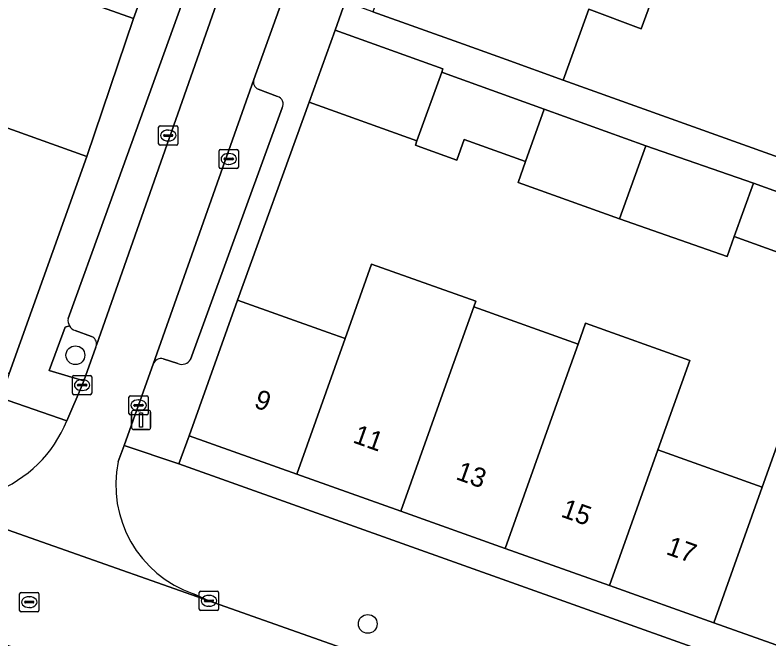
# Model space of a CAD drawing. Extents: x 159817 to 160765, y 380688 to 381638.
# Drawn here: x 160125.52 to 160164.67, y 381145.69 to 381178.1 of the extents above; entities that cross this region are included whole.
import ezdxf

# ---------------------------------------------------------------- set-up
doc = ezdxf.new("R2010")
doc.units = 0
for name, color, linetype in [('IMGEO_Boom', 7, 'Continuous'), ('IMGEO_Erf', 7, 'Continuous'), ('IMGEO_Groenvoorziening', 7, 'Continuous'), ('IMGEO_Kolk', 7, 'Continuous'), ('IMGEO_Lichtmast', 7, 'Continuous'), ('IMGEO_Muur', 7, 'Continuous'), ('IMGEO_Pand', 7, 'Continuous'), ('IMGEO_Pand_nummerreeks', 7, 'Continuous'), ('IMGEO_Parkeervlak_open', 7, 'Continuous'), ('IMGEO_Rijbaan_lokaal_open', 7, 'Continuous'), ('IMGEO_Rioolput', 7, 'Continuous'), ('IMGEO_Voetpad_open', 7, 'Continuous')]:
    doc.layers.add(name, color=color, linetype=linetype)

msp = doc.modelspace()

# ---------------------------------------------------------------- linework, layer by layer
at = {"layer": 'IMGEO_Boom'}
for centre in [(160128.655, 381160.427), (160143.838, 381146.472)]:
    msp.add_circle(centre, 0.489, dxfattribs=at)
at = {"layer": 'IMGEO_Erf'}
for points in [[(160166.279, 381209.298), (160163.437, 381210.329), (160161.369, 381204.579), (160164.234, 381203.614), (160162.154, 381197.83), (160163.066, 381197.502), (160161.69, 381193.674), (160164.512, 381192.675), (160163.836, 381190.794), (160160.049, 381192.134), (160157.986, 381186.396), (160159.888, 381185.712), (160158.664, 381182.309), (160161.844, 381181.165), (160160.986, 381178.778), (160158.826, 381179.555), (160158.045, 381177.383), (160155.316, 381178.399), (160153.991, 381174.716), (160170.088, 381168.945)], [(160123.783, 381172.701), (160129.244, 381170.748), (160131.673, 381177.921), (160128.045, 381179.223), (160126.309, 381179.846), (160127.288, 381182.577), (160125.277, 381183.178)], [(160166.219, 381165.378), (160162.869, 381166.591), (160162.497, 381165.563), (160156.911, 381167.504), (160151.65, 381169.403), (160152.036, 381170.487), (160148.85, 381171.637), (160148.464, 381170.553), (160146.587, 381171.231), (160146.312, 381171.33), (160146.394, 381171.558), (160140.795, 381173.569), (160137.079, 381163.29), (160141.789, 381161.611), (160142.658, 381161.3), (160144.034, 381165.16), (160149.449, 381163.23), (160149.345, 381162.937), (160154.762, 381161.006), (160155.149, 381162.091), (160160.566, 381160.16), (160158.907, 381155.508), (160164.323, 381153.577), (160166.602, 381159.968)]]:
    msp.add_lwpolyline(points, dxfattribs=at)
msp.add_lwpolyline([(160156.395, 381148.463), (160150.978, 381150.394), (160145.562, 381152.324), (160140.147, 381154.254), (160134.567, 381156.243), (160134.027, 381154.785), (160177.694, 381139.196), (160178.225, 381140.682), (160172.644, 381142.671), (160167.227, 381144.602), (160161.811, 381146.532)], close=True, dxfattribs=at)
at = {"layer": 'IMGEO_Groenvoorziening'}
for points in [[(160128.349, 381161.952), (160128.116, 381161.877), (160127.292, 381159.634), (160129.085, 381159.092), (160129.721, 381160.851)], [(160129.491, 381161.399), (160128.646, 381161.704)]]:
    msp.add_lwpolyline(points, dxfattribs=at)
for centre, radius, start, end in [((160128.851, 381162.251), 0.584, 210.7946, 249.4805), ((160129.342, 381161.014), 0.413, 350.1632, 68.7554), ((160129.293, 381161.026), 0.463, 337.8043, 349.8172)]:
    msp.add_arc(centre, radius, start, end, dxfattribs=at)
at = {"layer": 'IMGEO_Kolk'}
for p, q in [((160132.977, 381171.413), (160132.977, 381172.265)), ((160133.052, 381172.339), (160133.904, 381172.339)), ((160133.978, 381172.265), (160133.978, 381171.413)), ((160133.279, 381171.882), (160133.677, 381171.882)), ((160133.465, 381172.119), (160133.49, 381172.119)), ((160133.236, 381171.833), (160133.236, 381171.845)), ((160133.674, 381171.796), (160133.276, 381171.796)), ((160133.488, 381171.559), (160133.463, 381171.559)), ((160133.72, 381171.845), (160133.72, 381171.833)), ((160133.904, 381171.339), (160133.052, 381171.339)), ((160136.191, 381171.121), (160137.043, 381171.121)), ((160136.116, 381170.195), (160136.116, 381171.047)), ((160136.604, 381170.901), (160136.629, 381170.901)), ((160137.117, 381171.047), (160137.117, 381170.195)), ((160136.375, 381170.615), (160136.375, 381170.627)), ((160136.813, 381170.578), (160136.415, 381170.578)), ((160136.418, 381170.664), (160136.816, 381170.664)), ((160136.627, 381170.341), (160136.602, 381170.341)), ((160136.859, 381170.627), (160136.859, 381170.615)), ((160137.043, 381170.121), (160136.191, 381170.121)), ((160128.577, 381159.376), (160129.429, 381159.376)), ((160128.502, 381158.45), (160128.502, 381159.302)), ((160128.99, 381159.156), (160129.015, 381159.156)), ((160129.503, 381159.302), (160129.503, 381158.45)), ((160128.761, 381158.87), (160128.761, 381158.882)), ((160129.199, 381158.833), (160128.801, 381158.833)), ((160128.804, 381158.919), (160129.202, 381158.919)), ((160129.013, 381158.596), (160128.988, 381158.596)), ((160129.245, 381158.882), (160129.245, 381158.87)), ((160129.429, 381158.376), (160128.577, 381158.376)), ((160131.437, 381157.399), (160131.437, 381158.251)), ((160131.512, 381158.325), (160132.364, 381158.325)), ((160132.438, 381158.251), (160132.438, 381157.399)), ((160131.696, 381157.819), (160131.696, 381157.831)), ((160132.134, 381157.782), (160131.736, 381157.782)), ((160131.739, 381157.868), (160132.137, 381157.868)), ((160131.925, 381158.105), (160131.95, 381158.105)), ((160132.18, 381157.831), (160132.18, 381157.819)), ((160131.948, 381157.545), (160131.923, 381157.545)), ((160132.364, 381157.325), (160131.512, 381157.325)), ((160135.089, 381147.243), (160135.089, 381148.095)), ((160135.164, 381148.169), (160136.016, 381148.169)), ((160136.09, 381148.095), (160136.09, 381147.243)), ((160135.348, 381147.663), (160135.348, 381147.675)), ((160135.786, 381147.626), (160135.388, 381147.626)), ((160135.391, 381147.712), (160135.789, 381147.712)), ((160135.577, 381147.949), (160135.602, 381147.949)), ((160135.832, 381147.675), (160135.832, 381147.663)), ((160135.6, 381147.389), (160135.575, 381147.389)), ((160136.016, 381147.169), (160135.164, 381147.169))]:
    msp.add_line(p, q, dxfattribs=at)
for points in [[(160132.977, 381171.413), (160132.977, 381172.265)], [(160133.052, 381172.339), (160133.904, 381172.339)], [(160133.978, 381172.265), (160133.978, 381171.413)], [(160133.904, 381171.339), (160133.052, 381171.339)], [(160136.191, 381171.121), (160137.043, 381171.121)], [(160136.116, 381170.195), (160136.116, 381171.047)], [(160137.117, 381171.047), (160137.117, 381170.195)], [(160137.043, 381170.121), (160136.191, 381170.121)], [(160128.577, 381159.376), (160129.429, 381159.376)], [(160128.502, 381158.45), (160128.502, 381159.302)], [(160129.503, 381159.302), (160129.503, 381158.45)], [(160129.429, 381158.376), (160128.577, 381158.376)], [(160131.437, 381157.399), (160131.437, 381158.251)], [(160131.512, 381158.325), (160132.364, 381158.325)], [(160132.438, 381158.251), (160132.438, 381157.399)], [(160132.364, 381157.325), (160131.512, 381157.325)], [(160135.089, 381147.243), (160135.089, 381148.095)], [(160135.164, 381148.169), (160136.016, 381148.169)], [(160136.09, 381148.095), (160136.09, 381147.243)], [(160136.016, 381147.169), (160135.164, 381147.169)]]:
    msp.add_lwpolyline(points, dxfattribs=at)
for centre, radius, start, end in [((160133.054, 381172.263), 0.0765, 91.552, 178.448), ((160133.054, 381172.263), 0.0765, 91.552, 178.448), ((160133.902, 381172.263), 0.0765, 1.552, 88.448), ((160133.902, 381172.263), 0.0765, 1.552, 88.448), ((160133.276, 381171.842), 0.0403, 85.8775, 175.7526), ((160133.681, 381171.844), 0.0386, 1.7309, 96.639), ((160133.273, 381171.832), 0.0366, 178.938, 274.7102), ((160133.677, 381171.839), 0.043, 264.8664, 352.4533), ((160133.054, 381171.415), 0.0765, 181.552, 268.448), ((160133.054, 381171.415), 0.0765, 181.552, 268.448), ((160133.902, 381171.415), 0.0765, 271.552, 358.448), ((160133.902, 381171.415), 0.0765, 271.552, 358.448), ((160136.193, 381171.045), 0.0765, 91.552, 178.448), ((160136.193, 381171.045), 0.0765, 91.552, 178.448), ((160137.041, 381171.045), 0.0765, 1.552, 88.448), ((160137.041, 381171.045), 0.0765, 1.552, 88.448), ((160136.415, 381170.624), 0.0403, 85.8775, 175.7526), ((160136.412, 381170.614), 0.0366, 178.938, 274.7102), ((160136.816, 381170.621), 0.043, 264.8664, 352.4533), ((160136.82, 381170.626), 0.0386, 1.7309, 96.639), ((160136.193, 381170.197), 0.0765, 181.552, 268.448), ((160136.193, 381170.197), 0.0765, 181.552, 268.448), ((160137.041, 381170.197), 0.0765, 271.552, 358.448), ((160137.041, 381170.197), 0.0765, 271.552, 358.448), ((160128.579, 381159.3), 0.0765, 91.552, 178.448), ((160128.579, 381159.3), 0.0765, 91.552, 178.448), ((160129.427, 381159.3), 0.0765, 1.552, 88.448), ((160129.427, 381159.3), 0.0765, 1.552, 88.448), ((160128.801, 381158.879), 0.0403, 85.8775, 175.7526), ((160128.798, 381158.869), 0.0366, 178.938, 274.7102), ((160129.202, 381158.876), 0.043, 264.8664, 352.4533), ((160129.206, 381158.881), 0.0386, 1.7309, 96.639), ((160128.579, 381158.452), 0.0765, 181.552, 268.448), ((160128.579, 381158.452), 0.0765, 181.552, 268.448), ((160129.427, 381158.452), 0.0765, 271.552, 358.448), ((160129.427, 381158.452), 0.0765, 271.552, 358.448), ((160131.514, 381158.249), 0.0765, 91.552, 178.448), ((160131.514, 381158.249), 0.0765, 91.552, 178.448), ((160132.362, 381158.249), 0.0765, 1.552, 88.448), ((160132.362, 381158.249), 0.0765, 1.552, 88.448), ((160131.736, 381157.828), 0.0403, 85.8775, 175.7526), ((160131.733, 381157.818), 0.0366, 178.938, 274.7102), ((160132.137, 381157.825), 0.043, 264.8664, 352.4533), ((160132.141, 381157.83), 0.0386, 1.7309, 96.639), ((160131.514, 381157.401), 0.0765, 181.552, 268.448), ((160131.514, 381157.401), 0.0765, 181.552, 268.448), ((160132.362, 381157.401), 0.0765, 271.552, 358.448), ((160132.362, 381157.401), 0.0765, 271.552, 358.448), ((160135.166, 381148.093), 0.0765, 91.552, 178.448), ((160135.166, 381148.093), 0.0765, 91.552, 178.448), ((160136.014, 381148.093), 0.0765, 1.552, 88.448), ((160136.014, 381148.093), 0.0765, 1.552, 88.448), ((160135.388, 381147.672), 0.0403, 85.8775, 175.7526), ((160135.385, 381147.662), 0.0366, 178.938, 274.7102), ((160135.789, 381147.669), 0.043, 264.8664, 352.4533), ((160135.793, 381147.674), 0.0386, 1.7309, 96.639), ((160135.166, 381147.245), 0.0765, 181.552, 268.448), ((160135.166, 381147.245), 0.0765, 181.552, 268.448), ((160136.014, 381147.245), 0.0765, 271.552, 358.448), ((160136.014, 381147.245), 0.0765, 271.552, 358.448)]:
    msp.add_arc(centre, radius, start, end, dxfattribs=at)
for centre, major_axis, ratio, start_param, end_param in [((160133.464, 381171.839), (-0.387, 0.002), 0.722429, 4.712389, 7.853982), ((160133.489, 381171.839), (-0.39, 0.002), 0.717154, 1.570796, 4.712389), ((160136.603, 381170.621), (-0.387, 0.002), 0.722429, 4.712389, 7.853982), ((160136.628, 381170.621), (-0.39, 0.002), 0.717154, 1.570796, 4.712389), ((160128.989, 381158.876), (-0.387, 0.002), 0.722429, 4.712389, 7.853982), ((160129.014, 381158.876), (-0.39, 0.002), 0.717154, 1.570796, 4.712389), ((160131.924, 381157.825), (-0.387, 0.002), 0.722429, 4.712389, 7.853982), ((160131.949, 381157.825), (-0.39, 0.002), 0.717154, 1.570796, 4.712389), ((160135.576, 381147.669), (-0.387, 0.002), 0.722429, 4.712389, 7.853982), ((160135.601, 381147.669), (-0.39, 0.002), 0.717154, 1.570796, 4.712389)]:
    msp.add_ellipse(centre, major_axis=major_axis, ratio=ratio, start_param=start_param, end_param=end_param, dxfattribs=at)
at = {"layer": 'IMGEO_Lichtmast'}
for p, q in [((160131.569, 381156.667), (160131.569, 381157.467)), ((160131.569, 381157.467), (160131.569, 381156.667)), ((160131.669, 381157.567), (160132.459, 381157.567)), ((160132.459, 381157.567), (160131.669, 381157.567)), ((160132.559, 381157.467), (160132.559, 381156.667)), ((160132.559, 381156.667), (160132.559, 381157.467)), ((160132.459, 381156.567), (160131.669, 381156.567)), ((160131.669, 381156.567), (160132.459, 381156.567))]:
    msp.add_line(p, q, dxfattribs=at)
msp.add_lwpolyline([(160131.989, 381157.442), (160132.139, 381157.442), (160132.139, 381156.692), (160131.989, 381156.692), (160131.989, 381157.442)], dxfattribs=at)
for centre, start, end in [((160131.669, 381157.467), 90, 180), ((160131.669, 381157.467), 90, 180), ((160132.459, 381157.467), 0, 90), ((160132.459, 381157.467), 360, 90), ((160131.669, 381156.667), 180, 270), ((160131.669, 381156.667), 180, 270), ((160132.459, 381156.667), 270, 0), ((160132.459, 381156.667), 270, 0)]:
    msp.add_arc(centre, 0.1, start, end, dxfattribs=at)
at = {"layer": 'IMGEO_Muur'}
for points in [[(160129.244, 381170.748), (160131.673, 381177.921)], [(160137.079, 381163.29), (160140.795, 381173.569)]]:
    msp.add_lwpolyline(points, dxfattribs=at)
at = {"layer": 'IMGEO_Pand'}
for points in [[(160146.222, 381184.159), (160144.105, 381178.27), (160148.811, 381176.578), (160151.017, 381175.785), (160153.991, 381174.716), (160155.316, 381178.399), (160158.045, 381177.383), (160158.826, 381179.555)], [(160132.686, 381180.746), (160129.058, 381182.048), (160127.561, 381182.585), (160127.322, 381182.671), (160127.288, 381182.577), (160126.309, 381179.846), (160128.045, 381179.223), (160131.673, 381177.921)], [(160147.679, 381175.133), (160147.74, 381175.302), (160142.141, 381177.315), (160140.795, 381173.569), (160146.394, 381171.558)], [(160153.007, 381173.21), (160147.959, 381175.032), (160147.679, 381175.133), (160146.394, 381171.558), (160146.312, 381171.33), (160146.587, 381171.231), (160148.464, 381170.553), (160148.85, 381171.637), (160152.036, 381170.487)], [(160158.283, 381171.305), (160153.007, 381173.21), (160152.036, 381170.487), (160151.65, 381169.403), (160156.911, 381167.504)], [(160123.301, 381171.353), (160119.752, 381161.429), (160125.213, 381159.476), (160129.244, 381170.748), (160123.783, 381172.701)], [(160163.873, 381169.362), (160158.283, 381171.305), (160156.911, 381167.504), (160162.497, 381165.563), (160162.869, 381166.591)], [(160167.223, 381168.149), (160163.873, 381169.362), (160162.869, 381166.591), (160166.219, 381165.378)], [(160148.073, 381159.37), (160149.345, 381162.937), (160149.449, 381163.23), (160144.034, 381165.16), (160142.658, 381161.3), (160140.147, 381154.254), (160145.562, 381152.324)], [(160140.147, 381154.254), (160142.658, 381161.3), (160141.789, 381161.611), (160137.079, 381163.29), (160134.567, 381156.243)], [(160153.49, 381157.439), (160154.762, 381161.006), (160149.345, 381162.937), (160148.073, 381159.37), (160145.562, 381152.324), (160150.978, 381150.394)], [(160158.907, 381155.508), (160160.566, 381160.16), (160155.149, 381162.091), (160154.762, 381161.006), (160153.49, 381157.439), (160150.978, 381150.394), (160156.395, 381148.463)], [(160169.738, 381151.646), (160170.72, 381154.4), (160171.007, 381155.206), (160167.971, 381156.289), (160168.981, 381159.12), (160166.602, 381159.968), (160164.323, 381153.577), (160161.811, 381146.532), (160167.227, 381144.602)], [(160156.395, 381148.463), (160161.811, 381146.532), (160164.323, 381153.577), (160158.907, 381155.508)]]:
    msp.add_lwpolyline(points, close=True, dxfattribs=at)
at = {"layer": 'IMGEO_Parkeervlak_open'}
for points in [[(160135.047, 381181.09), (160130.24, 381167.741), (160128.272, 381162.329)], [(160129.748, 381160.944), (160136.536, 381180.276)], [(160137.923, 381174.746), (160132.696, 381159.965)], [(160139.15, 381173.873), (160138.141, 381174.242)], [(160134.64, 381160.204), (160139.391, 381173.277)], [(160128.646, 381161.704), (160129.491, 381161.399)], [(160133.22, 381160.243), (160133.982, 381159.991)]]:
    msp.add_lwpolyline(points, dxfattribs=at)
for centre, radius, start, end in [((160138.307, 381174.613), 0.406, 160.8667, 245.9141), ((160139.041, 381173.482), 0.406, 329.6308, 74.4023), ((160128.859, 381162.252), 0.591, 172.5619, 210.5252), ((160128.851, 381162.251), 0.584, 210.7946, 249.4805), ((160129.342, 381161.014), 0.413, 350.1632, 68.7554), ((160133.116, 381159.806), 0.449, 76.6465, 159.2485), ((160134.18, 381160.501), 0.547, 248.7372, 327.1372)]:
    msp.add_arc(centre, radius, start, end, dxfattribs=at)
at = {"layer": 'IMGEO_Rijbaan_lokaal_open'}
for points in [[(160137.923, 381174.746), (160139.551, 381179.287), (160136.536, 381180.276), (160129.748, 381160.944)], [(160130.876, 381154.914), (160131.18, 381155.746), (160131.938, 381157.825), (160132.696, 381159.965), (160137.923, 381174.746)], [(160135.586, 381147.67), (160119.463, 381153.345), (160119.152, 381153.556), (160118.335, 381153.851), (160095.277, 381162.239), (160088.059, 381164.786), (160087.951, 381164.723), (160087.876, 381164.68), (160087.437, 381164.424)], [(160129.721, 381160.851), (160129.085, 381159.092), (160129.003, 381158.876), (160128.206, 381157.021)], [(160085.799, 381159.896), (160085.986, 381159.435), (160086.066, 381159.245), (160086.112, 381159.128), (160093.302, 381156.554), (160121.03, 381146.824), (160125.069, 381145.386), (160156.523, 381134.111), (160186.491, 381123.368), (160203.779, 381117.171), (160205.8, 381122.85), (160205.469, 381122.967), (160135.586, 381147.67)], [(160119.152, 381153.556), (160119.463, 381153.345), (160135.586, 381147.67), (160134.786, 381148.029)]]:
    msp.add_lwpolyline(points, dxfattribs=at)
for centre, radius, start, end in [((160129.293, 381161.026), 0.463, 337.8043, 349.8172), ((160122.071, 381159.49), 6.613, 243.8097, 338.0744), ((160136.759, 381153.702), 6.006, 168.358, 250.8266)]:
    msp.add_arc(centre, radius, start, end, dxfattribs=at)
at = {"layer": 'IMGEO_Rioolput'}
for p, q in [((160125.759, 381147.176), (160125.759, 381148.028)), ((160125.834, 381148.102), (160126.686, 381148.102)), ((160126.76, 381148.028), (160126.76, 381147.176)), ((160126.018, 381147.596), (160126.018, 381147.608)), ((160126.061, 381147.645), (160126.459, 381147.645)), ((160126.247, 381147.882), (160126.272, 381147.882)), ((160126.502, 381147.608), (160126.502, 381147.596)), ((160126.456, 381147.559), (160126.058, 381147.559)), ((160126.27, 381147.322), (160126.245, 381147.322)), ((160126.686, 381147.102), (160125.834, 381147.102))]:
    msp.add_line(p, q, dxfattribs=at)
for points in [[(160125.759, 381147.176), (160125.759, 381148.028)], [(160125.834, 381148.102), (160126.686, 381148.102)], [(160126.76, 381148.028), (160126.76, 381147.176)], [(160126.686, 381147.102), (160125.834, 381147.102)]]:
    msp.add_lwpolyline(points, dxfattribs=at)
for centre, radius, start, end in [((160125.836, 381148.026), 0.0765, 91.552, 178.448), ((160125.836, 381148.026), 0.0765, 91.552, 178.448), ((160126.684, 381148.026), 0.0765, 1.552, 88.448), ((160126.684, 381148.026), 0.0765, 1.552, 88.448), ((160126.058, 381147.605), 0.0403, 85.8775, 175.7526), ((160126.055, 381147.595), 0.0366, 178.938, 274.7102), ((160126.459, 381147.602), 0.043, 264.8664, 352.4533), ((160126.463, 381147.607), 0.0386, 1.7309, 96.639), ((160125.836, 381147.178), 0.0765, 181.552, 268.448), ((160125.836, 381147.178), 0.0765, 181.552, 268.448), ((160126.684, 381147.178), 0.0765, 271.552, 358.448), ((160126.684, 381147.178), 0.0765, 271.552, 358.448)]:
    msp.add_arc(centre, radius, start, end, dxfattribs=at)
for centre, major_axis, ratio, start_param, end_param in [((160126.246, 381147.602), (-0.387, 0.002), 0.722429, 4.712389, 7.853982), ((160126.271, 381147.602), (-0.39, 0.002), 0.717154, 1.570796, 4.712389)]:
    msp.add_ellipse(centre, major_axis=major_axis, ratio=ratio, start_param=start_param, end_param=end_param, dxfattribs=at)
at = {"layer": 'IMGEO_Voetpad_open'}
for points in [[(160169.729, 381272.696), (160171.042, 381276.531), (160171.149, 381276.774), (160167.191, 381279.454), (160153.408, 381250), (160151.53, 381245.986), (160149.735, 381246.803), (160147.418, 381247.884), (160145.613, 381242.861), (160152.525, 381240.381), (160153.916, 381239.912), (160133.178, 381182.118), (160132.686, 381180.746), (160131.673, 381177.921), (160129.244, 381170.748), (160125.213, 381159.476), (160124.76, 381158.209), (160128.206, 381157.021), (160129.003, 381158.876), (160129.085, 381159.092), (160127.292, 381159.634), (160128.116, 381161.877), (160128.349, 381161.952)], [(160137.079, 381163.29), (160140.795, 381173.569), (160142.141, 381177.315), (160142.669, 381178.786), (160159.239, 381224.927), (160160.596, 381228.707), (160168.243, 381250), (160177.165, 381274.843), (160174.127, 381275.821), (160174.043, 381275.587), (160173.856, 381275.112), (160175.112, 381274.652), (160174.472, 381272.919), (160173.218, 381273.405), (160172.652, 381271.79)], [(160142.031, 381181.405), (160142.28, 381181.053), (160141.718, 381179.465), (160139.826, 381180.056), (160139.551, 381179.287), (160137.923, 381174.746)], [(160128.272, 381162.329), (160130.24, 381167.741), (160135.047, 381181.09)], [(160170.088, 381168.945), (160153.991, 381174.716), (160151.017, 381175.785), (160148.811, 381176.578), (160144.105, 381178.27), (160142.669, 381178.786), (160142.141, 381177.315), (160147.74, 381175.302), (160147.679, 381175.133), (160147.959, 381175.032), (160153.007, 381173.21), (160158.283, 381171.305), (160163.873, 381169.362), (160167.223, 381168.149)], [(160138.141, 381174.242), (160139.15, 381173.873)], [(160139.391, 381173.277), (160134.64, 381160.204)], [(160128.206, 381157.021), (160124.76, 381158.209), (160124.638, 381158.251), (160102.952, 381165.934)], [(160132.696, 381159.965), (160131.938, 381157.825), (160131.18, 381155.746), (160134.027, 381154.785), (160134.567, 381156.243), (160137.079, 381163.29)], [(160133.982, 381159.991), (160133.22, 381160.243)], [(160177.694, 381139.196), (160134.027, 381154.785), (160131.18, 381155.746), (160130.876, 381154.914)], [(160134.786, 381148.029), (160135.586, 381147.67), (160205.469, 381122.967), (160205.8, 381122.85)]]:
    msp.add_lwpolyline(points, dxfattribs=at)
for centre, radius, start, end in [((160138.307, 381174.613), 0.406, 160.8667, 245.9141), ((160139.041, 381173.482), 0.406, 329.6308, 74.4023), ((160128.859, 381162.252), 0.591, 172.5619, 210.5252), ((160133.116, 381159.806), 0.449, 76.6465, 159.2485), ((160134.18, 381160.501), 0.547, 248.7372, 327.1372), ((160122.071, 381159.49), 6.613, 243.8097, 338.0744), ((160136.759, 381153.702), 6.006, 168.358, 250.8266)]:
    msp.add_arc(centre, radius, start, end, dxfattribs=at)

# ---------------------------------------------------------------- texts
at = {"layer": 'IMGEO_Pand_nummerreeks'}
for s, rotation, p in [('9', 340.3824, (160137.882, 381157.736)), ('11', 340.3819, (160143.014, 381155.908)), ('13', 340.3819, (160148.363, 381154.001)), ('15', 340.3819, (160153.82, 381152.056)), ('17', 340.3824, (160159.278, 381150.111))]:
    msp.add_text(s, height=1, rotation=rotation, dxfattribs=at).set_placement(p)

doc.saveas('drawing.dxf')
